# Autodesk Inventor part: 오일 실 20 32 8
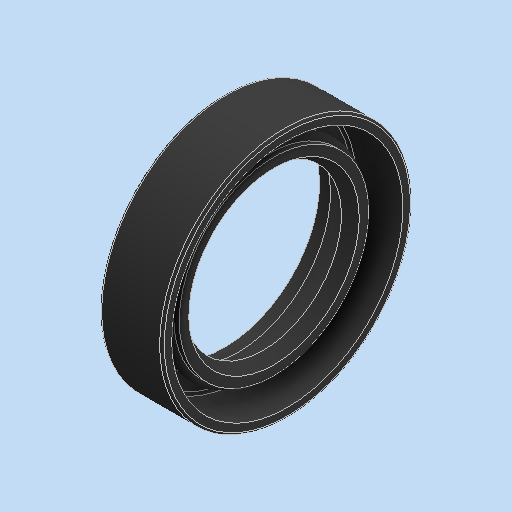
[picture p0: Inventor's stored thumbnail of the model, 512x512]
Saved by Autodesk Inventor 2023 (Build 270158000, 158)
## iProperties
Created: 2024-11
Part Number: 오일 실 20 32 8
Material: 고무
Description: 오일-실
Document SubType Name: Modeling
Designer: asung
Density: 0.93 g/cm^3
Appearance: 기본값
Author: jhkim
Sending System: Autodesk Inventor 2025
Preprocessor: ST-DEVELOPER v20
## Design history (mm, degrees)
feature "Solid1"
node "솔리드1"
